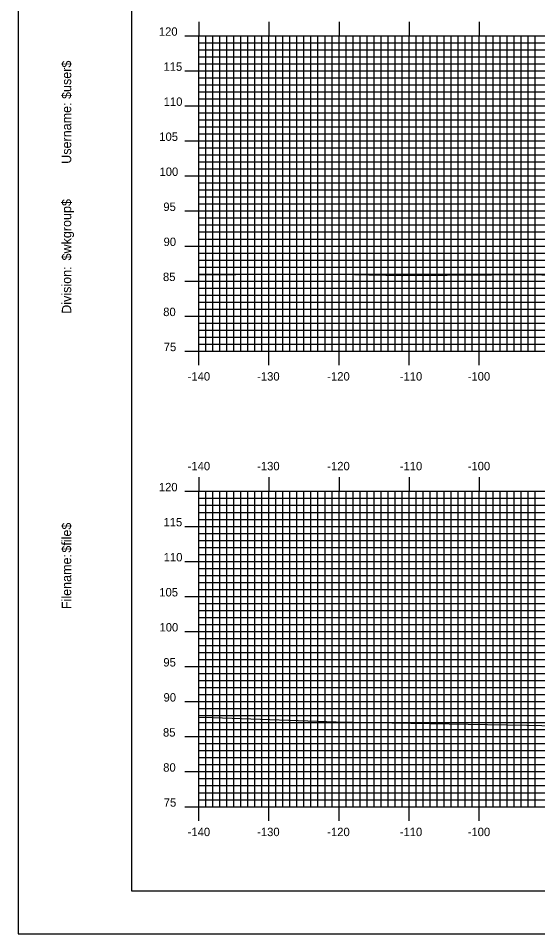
# Model space of a CAD drawing. Extents: x 855690 to 856034, y 364366 to 364586.
# Drawn here: x 855690.5 to 855764.6, y 364365.7 to 364496.3 of the extents above; entities that cross this region are included whole.
import ezdxf

# ---------------------------------------------------------------- set-up
doc = ezdxf.new("R2010")
doc.units = 0
for name, color, linetype in [('BORDER', 7, 'Continuous'), ('H_V ANNOTATION', 7, 'Continuous'), ('MAJOR', 7, 'Continuous'), ('MINOR', 7, 'Continuous'), ('PLOT BOUNDARY', 7, 'Continuous'), ('S_Roadway_Centerline', 7, 'Continuous')]:
    doc.layers.add(name, color=color, linetype=linetype)

msp = doc.modelspace()

# ---------------------------------------------------------------- linework, layer by layer
at = {"layer": 'BORDER'}
msp.add_lwpolyline([(855706.68, 364371.79), (856026.68, 364371.79), (856026.68, 364581.79), (855706.68, 364581.79)], close=True, dxfattribs=at)
at = {"layer": 'MAJOR'}
for p, q in [((855716.28, 364495.79), (855716.28, 364493.79)), ((855726.28, 364495.79), (855726.28, 364493.79)), ((855736.28, 364495.79), (855736.28, 364493.79)), ((855746.28, 364495.79), (855746.28, 364493.79)), ((855756.28, 364495.79), (855756.28, 364493.79)), ((855714.28, 364493.79), (855716.28, 364493.79)), ((855716.28, 364493.79), (855996.28, 364493.79)), ((855716.28, 364448.79), (855716.28, 364493.79)), ((855716.28, 364448.79), (855716.28, 364493.79)), ((855716.28, 364493.79), (855996.28, 364493.79)), ((855726.28, 364448.79), (855726.28, 364493.79)), ((855736.28, 364448.79), (855736.28, 364493.79)), ((855746.28, 364448.79), (855746.28, 364493.79)), ((855756.28, 364448.79), (855756.28, 364493.79)), ((855714.28, 364488.79), (855716.28, 364488.79)), ((855716.28, 364488.79), (855996.28, 364488.79)), ((855714.28, 364483.79), (855716.28, 364483.79)), ((855716.28, 364483.79), (855996.28, 364483.79)), ((855714.28, 364478.79), (855716.28, 364478.79)), ((855716.28, 364478.79), (855996.28, 364478.79)), ((855714.28, 364473.79), (855716.28, 364473.79)), ((855716.28, 364473.79), (855996.28, 364473.79)), ((855714.28, 364468.79), (855716.28, 364468.79)), ((855716.28, 364468.79), (855996.28, 364468.79)), ((855714.28, 364463.79), (855716.28, 364463.79)), ((855716.28, 364463.79), (855996.28, 364463.79)), ((855714.28, 364458.79), (855716.28, 364458.79)), ((855716.28, 364458.79), (855996.28, 364458.79)), ((855714.28, 364453.79), (855716.28, 364453.79)), ((855716.28, 364453.79), (855996.28, 364453.79)), ((855714.28, 364448.79), (855716.28, 364448.79)), ((855716.28, 364448.79), (855996.28, 364448.79)), ((855716.28, 364448.79), (855996.28, 364448.79)), ((855716.28, 364446.78), (855716.28, 364448.79)), ((855726.28, 364446.78), (855726.28, 364448.79)), ((855736.28, 364446.78), (855736.28, 364448.79)), ((855746.28, 364446.78), (855746.28, 364448.79)), ((855756.28, 364446.78), (855756.28, 364448.79)), ((855716.28, 364430.79), (855716.28, 364428.79)), ((855726.28, 364430.79), (855726.28, 364428.79)), ((855736.28, 364430.79), (855736.28, 364428.79)), ((855746.28, 364430.79), (855746.28, 364428.79)), ((855756.28, 364430.79), (855756.28, 364428.79)), ((855714.28, 364428.79), (855716.28, 364428.79)), ((855716.28, 364428.79), (855996.28, 364428.79)), ((855716.28, 364383.79), (855716.28, 364428.79)), ((855716.28, 364383.79), (855716.28, 364428.79)), ((855716.28, 364428.79), (855996.28, 364428.79)), ((855726.28, 364383.79), (855726.28, 364428.79)), ((855736.28, 364383.79), (855736.28, 364428.79)), ((855746.28, 364383.79), (855746.28, 364428.79)), ((855756.28, 364383.79), (855756.28, 364428.79)), ((855714.28, 364423.79), (855716.28, 364423.79)), ((855716.28, 364423.79), (855996.28, 364423.79)), ((855714.28, 364418.79), (855716.28, 364418.79)), ((855716.28, 364418.79), (855996.28, 364418.79)), ((855714.28, 364413.79), (855716.28, 364413.79)), ((855716.28, 364413.79), (855996.28, 364413.79)), ((855714.28, 364408.79), (855716.28, 364408.79)), ((855716.28, 364408.79), (855996.28, 364408.79)), ((855714.28, 364403.79), (855716.28, 364403.79)), ((855716.28, 364403.79), (855996.28, 364403.79)), ((855714.28, 364398.79), (855716.28, 364398.79)), ((855716.28, 364398.79), (855996.28, 364398.79)), ((855714.28, 364393.79), (855716.28, 364393.79)), ((855716.28, 364393.79), (855996.28, 364393.79)), ((855714.28, 364388.79), (855716.28, 364388.79)), ((855716.28, 364388.79), (855996.28, 364388.79)), ((855714.28, 364383.79), (855716.28, 364383.79)), ((855716.28, 364383.79), (855996.28, 364383.79)), ((855716.28, 364383.79), (855996.28, 364383.79)), ((855716.28, 364381.78), (855716.28, 364383.79)), ((855726.28, 364381.78), (855726.28, 364383.79)), ((855736.28, 364381.78), (855736.28, 364383.79)), ((855746.28, 364381.78), (855746.28, 364383.79)), ((855756.28, 364381.78), (855756.28, 364383.79))]:
    msp.add_line(p, q, dxfattribs=at)
at = {"layer": 'MINOR'}
for p, q in [((855717.28, 364448.79), (855717.28, 364493.79)), ((855718.28, 364448.79), (855718.28, 364493.79)), ((855719.28, 364448.79), (855719.28, 364493.79)), ((855720.28, 364448.79), (855720.28, 364493.79)), ((855721.28, 364448.79), (855721.28, 364493.79)), ((855722.28, 364448.79), (855722.28, 364493.79)), ((855723.28, 364448.79), (855723.28, 364493.79)), ((855724.28, 364448.79), (855724.28, 364493.79)), ((855725.28, 364448.79), (855725.28, 364493.79)), ((855727.28, 364448.79), (855727.28, 364493.79)), ((855728.28, 364448.79), (855728.28, 364493.79)), ((855729.28, 364448.79), (855729.28, 364493.79)), ((855730.28, 364448.79), (855730.28, 364493.79)), ((855731.28, 364448.79), (855731.28, 364493.79)), ((855732.28, 364448.79), (855732.28, 364493.79)), ((855733.28, 364448.79), (855733.28, 364493.79)), ((855734.28, 364448.79), (855734.28, 364493.79)), ((855735.28, 364448.79), (855735.28, 364493.79)), ((855737.28, 364448.79), (855737.28, 364493.79)), ((855738.28, 364448.79), (855738.28, 364493.79)), ((855739.28, 364448.79), (855739.28, 364493.79)), ((855740.28, 364448.79), (855740.28, 364493.79)), ((855741.28, 364448.79), (855741.28, 364493.79)), ((855742.28, 364448.79), (855742.28, 364493.79)), ((855743.28, 364448.79), (855743.28, 364493.79)), ((855744.28, 364448.79), (855744.28, 364493.79)), ((855745.28, 364448.79), (855745.28, 364493.79)), ((855747.28, 364448.79), (855747.28, 364493.79)), ((855748.28, 364448.79), (855748.28, 364493.79)), ((855749.28, 364448.79), (855749.28, 364493.79)), ((855750.28, 364448.79), (855750.28, 364493.79)), ((855751.28, 364448.79), (855751.28, 364493.79)), ((855752.28, 364448.79), (855752.28, 364493.79)), ((855753.28, 364448.79), (855753.28, 364493.79)), ((855754.28, 364448.79), (855754.28, 364493.79)), ((855755.28, 364448.79), (855755.28, 364493.79)), ((855757.28, 364448.79), (855757.28, 364493.79)), ((855758.28, 364448.79), (855758.28, 364493.79)), ((855759.28, 364448.79), (855759.28, 364493.79)), ((855760.28, 364448.79), (855760.28, 364493.79)), ((855761.28, 364448.79), (855761.28, 364493.79)), ((855762.28, 364448.79), (855762.28, 364493.79)), ((855763.28, 364448.79), (855763.28, 364493.79)), ((855764.28, 364448.79), (855764.28, 364493.79)), ((855716.28, 364492.79), (855996.28, 364492.79)), ((855716.28, 364492.79), (855718.29, 364492.79)), ((855716.28, 364491.79), (855996.28, 364491.79)), ((855716.28, 364491.79), (855718.29, 364491.79)), ((855716.28, 364490.79), (855996.28, 364490.79)), ((855716.28, 364490.79), (855718.29, 364490.79)), ((855716.28, 364489.79), (855996.28, 364489.79)), ((855716.28, 364489.79), (855718.29, 364489.79)), ((855716.28, 364487.79), (855996.28, 364487.79)), ((855716.28, 364487.79), (855718.29, 364487.79)), ((855716.28, 364486.79), (855996.28, 364486.79)), ((855716.28, 364486.79), (855718.29, 364486.79)), ((855716.28, 364485.79), (855996.28, 364485.79)), ((855716.28, 364485.79), (855718.29, 364485.79)), ((855716.28, 364484.79), (855996.28, 364484.79)), ((855716.28, 364484.79), (855718.29, 364484.79)), ((855716.28, 364482.79), (855996.28, 364482.79)), ((855716.28, 364482.79), (855718.29, 364482.79)), ((855716.28, 364481.79), (855996.28, 364481.79)), ((855716.28, 364481.79), (855718.29, 364481.79)), ((855716.28, 364480.79), (855996.28, 364480.79)), ((855716.28, 364480.79), (855718.29, 364480.79)), ((855716.28, 364479.79), (855996.28, 364479.79)), ((855716.28, 364479.79), (855718.29, 364479.79)), ((855716.28, 364477.79), (855996.28, 364477.79)), ((855716.28, 364477.79), (855718.29, 364477.79)), ((855716.28, 364476.79), (855996.28, 364476.79)), ((855716.28, 364476.79), (855718.29, 364476.79)), ((855716.28, 364475.79), (855996.28, 364475.79)), ((855716.28, 364475.79), (855718.29, 364475.79)), ((855716.28, 364474.79), (855996.28, 364474.79)), ((855716.28, 364474.79), (855718.29, 364474.79)), ((855716.28, 364472.79), (855996.28, 364472.79)), ((855716.28, 364472.79), (855718.29, 364472.79)), ((855716.28, 364471.79), (855996.28, 364471.79)), ((855716.28, 364471.79), (855718.29, 364471.79)), ((855716.28, 364470.79), (855996.28, 364470.79)), ((855716.28, 364470.79), (855718.29, 364470.79)), ((855716.28, 364469.79), (855996.28, 364469.79)), ((855716.28, 364469.79), (855718.29, 364469.79)), ((855716.28, 364467.79), (855996.28, 364467.79)), ((855716.28, 364467.79), (855718.29, 364467.79)), ((855716.28, 364466.79), (855996.28, 364466.79)), ((855716.28, 364466.79), (855718.29, 364466.79)), ((855716.28, 364465.79), (855996.28, 364465.79)), ((855716.28, 364465.79), (855718.29, 364465.79)), ((855716.28, 364464.79), (855996.28, 364464.79)), ((855716.28, 364464.79), (855718.29, 364464.79)), ((855716.28, 364462.79), (855996.28, 364462.79)), ((855716.28, 364462.79), (855718.29, 364462.79)), ((855716.28, 364461.79), (855996.28, 364461.79)), ((855716.28, 364461.79), (855718.29, 364461.79)), ((855716.28, 364460.79), (855996.28, 364460.79)), ((855716.28, 364460.79), (855718.29, 364460.79)), ((855716.28, 364459.79), (855996.28, 364459.79)), ((855716.28, 364459.79), (855718.29, 364459.79)), ((855716.28, 364457.79), (855996.28, 364457.79)), ((855716.28, 364457.79), (855718.29, 364457.79)), ((855716.28, 364456.79), (855996.28, 364456.79)), ((855716.28, 364456.79), (855718.29, 364456.79)), ((855716.28, 364455.79), (855996.28, 364455.79)), ((855716.28, 364455.79), (855718.29, 364455.79)), ((855716.28, 364454.79), (855996.28, 364454.79)), ((855716.28, 364454.79), (855718.29, 364454.79)), ((855716.28, 364452.79), (855996.28, 364452.79)), ((855716.28, 364452.79), (855718.29, 364452.79)), ((855716.28, 364451.79), (855996.28, 364451.79)), ((855716.28, 364451.79), (855718.29, 364451.79)), ((855716.28, 364450.79), (855996.28, 364450.79)), ((855716.28, 364450.79), (855718.29, 364450.79)), ((855716.28, 364449.79), (855996.28, 364449.79)), ((855716.28, 364449.79), (855718.29, 364449.79)), ((855716.28, 364427.79), (855996.28, 364427.79)), ((855716.28, 364427.79), (855718.29, 364427.79)), ((855717.28, 364383.79), (855717.28, 364428.79)), ((855718.28, 364383.79), (855718.28, 364428.79)), ((855719.28, 364383.79), (855719.28, 364428.79)), ((855720.28, 364383.79), (855720.28, 364428.79)), ((855721.28, 364383.79), (855721.28, 364428.79)), ((855722.28, 364383.79), (855722.28, 364428.79)), ((855723.28, 364383.79), (855723.28, 364428.79)), ((855724.28, 364383.79), (855724.28, 364428.79)), ((855725.28, 364383.79), (855725.28, 364428.79)), ((855727.28, 364383.79), (855727.28, 364428.79)), ((855728.28, 364383.79), (855728.28, 364428.79)), ((855729.28, 364383.79), (855729.28, 364428.79)), ((855730.28, 364383.79), (855730.28, 364428.79)), ((855731.28, 364383.79), (855731.28, 364428.79)), ((855732.28, 364383.79), (855732.28, 364428.79)), ((855733.28, 364383.79), (855733.28, 364428.79)), ((855734.28, 364383.79), (855734.28, 364428.79)), ((855735.28, 364383.79), (855735.28, 364428.79)), ((855737.28, 364383.79), (855737.28, 364428.79)), ((855738.28, 364383.79), (855738.28, 364428.79)), ((855739.28, 364383.79), (855739.28, 364428.79)), ((855740.28, 364383.79), (855740.28, 364428.79)), ((855741.28, 364383.79), (855741.28, 364428.79)), ((855742.28, 364383.79), (855742.28, 364428.79)), ((855743.28, 364383.79), (855743.28, 364428.79)), ((855744.28, 364383.79), (855744.28, 364428.79)), ((855745.28, 364383.79), (855745.28, 364428.79)), ((855747.28, 364383.79), (855747.28, 364428.79)), ((855748.28, 364383.79), (855748.28, 364428.79)), ((855749.28, 364383.79), (855749.28, 364428.79)), ((855750.28, 364383.79), (855750.28, 364428.79)), ((855751.28, 364383.79), (855751.28, 364428.79)), ((855752.28, 364383.79), (855752.28, 364428.79)), ((855753.28, 364383.79), (855753.28, 364428.79)), ((855754.28, 364383.79), (855754.28, 364428.79)), ((855755.28, 364383.79), (855755.28, 364428.79)), ((855757.28, 364383.79), (855757.28, 364428.79)), ((855758.28, 364383.79), (855758.28, 364428.79)), ((855759.28, 364383.79), (855759.28, 364428.79)), ((855760.28, 364383.79), (855760.28, 364428.79)), ((855761.28, 364383.79), (855761.28, 364428.79)), ((855762.28, 364383.79), (855762.28, 364428.79)), ((855763.28, 364383.79), (855763.28, 364428.79)), ((855764.28, 364383.79), (855764.28, 364428.79)), ((855716.28, 364426.79), (855996.28, 364426.79)), ((855716.28, 364426.79), (855718.29, 364426.79)), ((855716.28, 364425.79), (855996.28, 364425.79)), ((855716.28, 364425.79), (855718.29, 364425.79)), ((855716.28, 364424.79), (855996.28, 364424.79)), ((855716.28, 364424.79), (855718.29, 364424.79)), ((855716.28, 364422.79), (855996.28, 364422.79)), ((855716.28, 364422.79), (855718.29, 364422.79)), ((855716.28, 364421.79), (855996.28, 364421.79)), ((855716.28, 364421.79), (855718.29, 364421.79)), ((855716.28, 364420.79), (855996.28, 364420.79)), ((855716.28, 364420.79), (855718.29, 364420.79)), ((855716.28, 364419.79), (855996.28, 364419.79)), ((855716.28, 364419.79), (855718.29, 364419.79)), ((855716.28, 364417.79), (855996.28, 364417.79)), ((855716.28, 364417.79), (855718.29, 364417.79)), ((855716.28, 364416.79), (855996.28, 364416.79)), ((855716.28, 364416.79), (855718.29, 364416.79)), ((855716.28, 364415.79), (855996.28, 364415.79)), ((855716.28, 364415.79), (855718.29, 364415.79)), ((855716.28, 364414.79), (855996.28, 364414.79)), ((855716.28, 364414.79), (855718.29, 364414.79)), ((855716.28, 364412.79), (855996.28, 364412.79)), ((855716.28, 364412.79), (855718.29, 364412.79)), ((855716.28, 364411.79), (855996.28, 364411.79)), ((855716.28, 364411.79), (855718.29, 364411.79)), ((855716.28, 364410.79), (855996.28, 364410.79)), ((855716.28, 364410.79), (855718.29, 364410.79)), ((855716.28, 364409.79), (855996.28, 364409.79)), ((855716.28, 364409.79), (855718.29, 364409.79)), ((855716.28, 364407.79), (855996.28, 364407.79)), ((855716.28, 364407.79), (855718.29, 364407.79)), ((855716.28, 364406.79), (855996.28, 364406.79)), ((855716.28, 364406.79), (855718.29, 364406.79)), ((855716.28, 364405.79), (855996.28, 364405.79)), ((855716.28, 364405.79), (855718.29, 364405.79)), ((855716.28, 364404.79), (855996.28, 364404.79)), ((855716.28, 364404.79), (855718.29, 364404.79)), ((855716.28, 364402.79), (855996.28, 364402.79)), ((855716.28, 364402.79), (855718.29, 364402.79)), ((855716.28, 364401.79), (855996.28, 364401.79)), ((855716.28, 364401.79), (855718.29, 364401.79)), ((855716.28, 364400.79), (855996.28, 364400.79)), ((855716.28, 364400.79), (855718.29, 364400.79)), ((855716.28, 364399.79), (855996.28, 364399.79)), ((855716.28, 364399.79), (855718.29, 364399.79)), ((855716.28, 364397.79), (855996.28, 364397.79)), ((855716.28, 364397.79), (855718.29, 364397.79)), ((855716.28, 364396.79), (855996.28, 364396.79)), ((855716.28, 364396.79), (855718.29, 364396.79)), ((855716.28, 364395.79), (855996.28, 364395.79)), ((855716.28, 364395.79), (855718.29, 364395.79)), ((855716.28, 364394.79), (855996.28, 364394.79)), ((855716.28, 364394.79), (855718.29, 364394.79)), ((855716.28, 364392.79), (855996.28, 364392.79)), ((855716.28, 364392.79), (855718.29, 364392.79)), ((855716.28, 364391.79), (855996.28, 364391.79)), ((855716.28, 364391.79), (855718.29, 364391.79)), ((855716.28, 364390.79), (855996.28, 364390.79)), ((855716.28, 364390.79), (855718.29, 364390.79)), ((855716.28, 364389.79), (855996.28, 364389.79)), ((855716.28, 364389.79), (855718.29, 364389.79)), ((855716.28, 364387.79), (855996.28, 364387.79)), ((855716.28, 364387.79), (855718.29, 364387.79)), ((855716.28, 364386.79), (855996.28, 364386.79)), ((855716.28, 364386.79), (855718.29, 364386.79)), ((855716.28, 364385.79), (855996.28, 364385.79)), ((855716.28, 364385.79), (855718.29, 364385.79)), ((855716.28, 364384.79), (855996.28, 364384.79)), ((855716.28, 364384.79), (855718.29, 364384.79))]:
    msp.add_line(p, q, dxfattribs=at)
at = {"layer": 'PLOT BOUNDARY'}
msp.add_lwpolyline([(855690.5, 364365.67), (856030.5, 364365.67), (856030.5, 364585.67), (855690.5, 364585.67)], close=True, dxfattribs=at)
at = {"layer": 'S_Roadway_Centerline'}
for points in [[(855716.28, 364459.71), (855721.54, 364459.71), (855736.38, 364459.78), (855740.54, 364459.68), (855745.4, 364459.58), (855764.38, 364459.71), (855768.57, 364459.49), (855782.16, 364458.94), (855786.89, 364459), (855791.64, 364459.04), (855805.12, 364459.05), (855810.51, 364459), (855816.17, 364458.91), (855822.08, 364458.96), (855827.51, 364458.73), (855834.03, 364458.61), (855840.8, 364458.61)], [(855716.28, 364396.58), (855718.3, 364396.5), (855737.2, 364395.84), (855738.26, 364395.83), (855743.8, 364395.75), (855760.2, 364395.47), (855763.11, 364395.42), (855780.07, 364395.03), (855784.13, 364394.9), (855789.62, 364395.01), (855796.66, 364395.01), (855801.4, 364394.98), (855815.99, 364394.6), (855819.85, 364394.55), (855823.07, 364394.55), (855831.57, 364394.47), (855842.14, 364394.32)]]:
    msp.add_lwpolyline(points, dxfattribs=at)

# ---------------------------------------------------------------- texts
at = {"layer": 'BORDER'}
for s, p in [('$user$', (855698.05, 364484.77)), ('Username:', (855698.05, 364475.52)), ('$wkgroup$', (855698.05, 364461.73)), ('Division:', (855698.05, 364454.12)), ('$file$', (855698.05, 364420.04)), ('Filename:', (855698.05, 364411.98))]:
    msp.add_text(s, height=1.339, rotation=90, dxfattribs=at).set_placement(p)
at = {"layer": 'H_V ANNOTATION'}
for s, p in [('120', (855710.56, 364493.79)), ('115', (855711.22, 364488.79)), ('110', (855711.25, 364483.79)), ('105', (855710.62, 364478.79)), ('100', (855710.65, 364473.79)), ('95', (855711.2, 364468.79)), ('90', (855711.23, 364463.79)), ('85', (855711.15, 364458.79)), ('80', (855711.18, 364453.79)), ('75', (855711.26, 364448.79)), ('-140', (855714.67, 364444.59)), ('-130', (855724.59, 364444.59)), ('-120', (855734.6, 364444.59)), ('-110', (855744.95, 364444.59)), ('-100', (855754.65, 364444.59)), ('-140', (855714.67, 364431.79)), ('-130', (855724.59, 364431.79)), ('-120', (855734.6, 364431.79)), ('-110', (855744.95, 364431.79)), ('-100', (855754.65, 364431.79)), ('120', (855710.56, 364428.79)), ('115', (855711.22, 364423.79)), ('110', (855711.25, 364418.79)), ('105', (855710.62, 364413.79)), ('100', (855710.65, 364408.79)), ('95', (855711.2, 364403.79)), ('90', (855711.23, 364398.79)), ('85', (855711.15, 364393.79)), ('80', (855711.18, 364388.79)), ('75', (855711.26, 364383.79)), ('-140', (855714.67, 364379.59)), ('-130', (855724.59, 364379.59)), ('-120', (855734.6, 364379.59)), ('-110', (855744.95, 364379.59)), ('-100', (855754.65, 364379.59))]:
    msp.add_text(s, height=1.2, dxfattribs=at).set_placement(p)
at = {"layer": 'MAJOR'}
for p in [(855716.27, 364448.79), (855716.27, 364383.79)]:
    msp.add_text('-', height=0.012, dxfattribs=at).set_placement(p)

doc.saveas('drawing.dxf')
